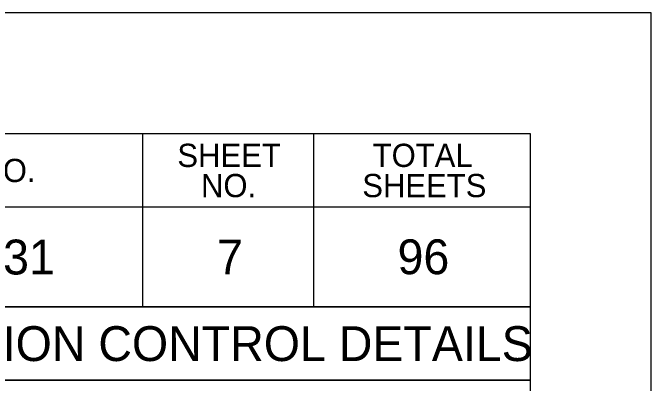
# Model space of a CAD drawing. Extents: x -0.29 to 1.42, y 0 to 0.92.
# Drawn here: x 1.3066 to 1.4167, y 0.8529 to 0.9167 of the extents above; entities that cross this region are included whole.
import ezdxf

# ---------------------------------------------------------------- set-up
doc = ezdxf.new("R2010")
doc.units = 0
for name, color, linetype in [('DSN_DRFT_Guideline-No-Plot', 7, 'Continuous'), ('SHET_Annotations', 7, 'Continuous'), ('SHET_Border-Lines', 7, 'Continuous'), ('SHET_Border-Text', 7, 'Continuous')]:
    doc.layers.add(name, color=color, linetype=linetype)

msp = doc.modelspace()

# ---------------------------------------------------------------- linework, layer by layer
at = {"layer": 'DSN_DRFT_Guideline-No-Plot'}
msp.add_lwpolyline([(0, 0), (1.416666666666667, 0), (1.416666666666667, 0.9166666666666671), (0, 0.9166666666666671)], close=True, dxfattribs=at)
at = {"layer": 'SHET_Border-Lines'}
for p, q in [((1.328939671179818, 0.8958333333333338), (1.328939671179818, 0.8660136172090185)), ((1.358434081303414, 0.8958333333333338), (1.358434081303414, 0.8660136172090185)), ((1.3958333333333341, 0.8832007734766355), (1.2126619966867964, 0.8832007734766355)), ((1.3958333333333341, 0.8832867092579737), (1.3958333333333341, 0.8832867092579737)), ((1.3958333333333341, 0.8660136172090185), (1.2126619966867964, 0.8660136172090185)), ((1.2252417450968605, 0.8660136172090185), (1.3958333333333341, 0.8660136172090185)), ((1.3958333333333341, 0.8533810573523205), (1.1296186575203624, 0.8533810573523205))]:
    msp.add_line(p, q, dxfattribs=at)
for points in [[(0.02083333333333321, 0.02083333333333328), (1.3958333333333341, 0.02083333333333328), (1.3958333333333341, 0.8958333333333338), (0.02083333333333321, 0.8958333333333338)], [(1.1296186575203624, 0.8533810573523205), (1.3958333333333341, 0.8533810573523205), (1.3958333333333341, 0.8958333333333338), (1.1296186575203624, 0.8958333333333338)]]:
    msp.add_lwpolyline(points, close=True, dxfattribs=at)

# ---------------------------------------------------------------- texts
at = {"layer": 'SHET_Annotations'}
for s, p in [('110831', (1.2870604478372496, 0.8716071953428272)), ('7', (1.3418089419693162, 0.8716071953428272)), ('96', (1.3729220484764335, 0.8716501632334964)), ('TEMPORARY EROSION CONTROL DETAILS', (1.2290559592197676, 0.8566973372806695))]:
    msp.add_text(s, height=0.006000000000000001, dxfattribs=at).set_placement(p)
at = {"layer": 'SHET_Border-Text'}
for s, p in [('SHEET', (1.3349584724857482, 0.8901170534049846)), ('TOTAL', (1.3686372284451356, 0.8901170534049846)), ('JOB NO.', (1.2891034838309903, 0.8875170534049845)), ('NO.', (1.3390335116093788, 0.8849170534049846)), ('SHEETS', (1.3668472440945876, 0.8849170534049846))]:
    msp.add_text(s, height=0.004, dxfattribs=at).set_placement(p)

doc.saveas('drawing.dxf')
